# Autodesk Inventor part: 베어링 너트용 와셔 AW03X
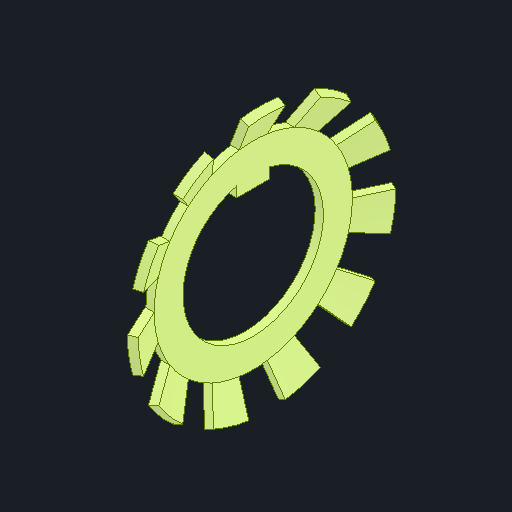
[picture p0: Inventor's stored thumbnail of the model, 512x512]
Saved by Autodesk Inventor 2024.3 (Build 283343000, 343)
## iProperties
Created: 2025-03
Part Number: 베어링 너트용 와셔 AW03X
Material: 강철, 연강
Description: 잠금 와셔
Document SubType Name: Modeling
Designer: user
Density: 7.85 g/cm^3
Appearance: 기본값
Author: jhkim
Sending System: Autodesk Inventor 2025
Preprocessor: ST-DEVELOPER v20
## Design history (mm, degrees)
feature "Solid1"
node "솔리드1"
